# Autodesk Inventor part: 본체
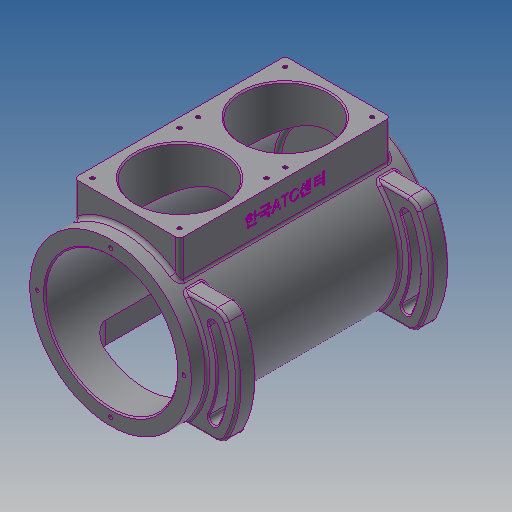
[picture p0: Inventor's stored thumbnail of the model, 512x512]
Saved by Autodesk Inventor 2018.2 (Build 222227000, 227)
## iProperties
Created: 2016-11
Part Number: 본체
Material: 알루미늄 6061
Document SubType Name: Modeling
Designer: mduedu
Density: 2.71 g/cm^3
Appearance: 기본값
Author: mduedu
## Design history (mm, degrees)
sketch "스케치1"
  geometry: C1 r 65 at (0, 0); 1 further point
  constraints: 1 centre point, 1 coincident
  dimensions: "d119" = 130 diameter of C1
extrude "돌출1" new body sketch "스케치1" distance "d3" = 98; taper "d4" = 0 deg; dims "d132" = 97, "d133" = 0
feature "쉘1" dims "d120" = 12, "d134" = 8
node "작업 평면2"
sketch "스케치13"
  geometry: L1 (42.5, 85)-(-42.5, 85); L2 (-42.5, 85)-(-42.5, -85); L3 (-42.5, -85)-(42.5, -85); L4 (42.5, -85)-(42.5, 85); 2 further points
  constraints: 8 end point, 2 parallel, 1 horizontal, 1 midpoint, 1 perpendicular, 1 vertical alignment
  dimensions: "d122" = 170 distance of L1.end L2.end; "d124" = 85 distance of L2.end L3.end; "d125" = 85 distance from line of point (0, 0) L1 (= 0.5 x d122)
extrude "돌출11" join sketch "스케치13" stored distance "d126" = 10; taper "d127" = 0 deg
sketch "스케치14"
  geometry: L1 (65, 97)-(-65, 97) reference; C1 r 35 at (0, 42.5); 1 further point
  constraints: 1 centre point, 1 vertical alignment
  dimensions: "d128" = 70 diameter of C1; "d129" = 54.5 distance from line of C1.centre L1
extrude "돌출12" cut sketch "스케치14" stored distance "d130" = 10; taper "d131" = 0 deg
sketch "스케치15"
  geometry: C1 r 53 at (0, 0) reference; 1 further point
extrude "돌출13" cut sketch "스케치15" stored distance "d135" = 10; taper "d136" = 0 deg
chamfer "모따기1" distance "d54" = 1; stored, may be unused: second distance "d55" = 2, angle "d56" = 45 deg
sketch "스케치8"
  geometry: C1 r 30 at (0, 0); C2 r 65 at (0, 0) reference; 1 further point
  constraints: 1 centre point, 1 concentric
  dimensions: "d57" = 60 diameter of C1
extrude "돌출8" join sketch "스케치8" distance "d58" = 14; taper "d59" = 0 deg
hole "구멍3" diameter "d62" = 41; stored, may be unused: countersink angle "d66" = 90 deg, drill point angle "d68" = 0 deg; dims "d63" = 6, "d64" = 47, "d65" = 14, "d67" = 17, "d195" = 10, "d196" = 10
fillet "모깎기11" dims "d69" = 3
fillet "모깎기12" dims "d70" = 3
fillet "모깎기13" dims "d71" = 0.3
chamfer "모따기2" distance "d72" = 1; stored, may be unused: second distance "d73" = 2, angle "d74" = 45 deg
node "작업 평면3"
sketch "스케치16"
  geometry: L1 (-42.5, -80)-(47.5, -80); L2 (-42.5, -80)-(21.14, -16.36); L3 (-42.5, -80)-(21.14, -143.64); L4 (3.462, -34.038)-(34.879, -34.038); L5 (3.462, -125.962)-(34.879, -125.962); A1 r 65 centre (-42.5, -80) between (3.462, -34.038) and (3.462, -125.962) reference; A2 r 90 centre (-42.5, -80) between (34.879, -125.962) and (34.879, -34.038); A3 r 90 centre (-42.5, -80) between (34.879, -34.038) and (34.879, -125.962); A4 r 65 centre (-42.5, -80) between (3.462, -125.962) and (3.462, -34.038); 1 further point
  constraints: 11 point on circle, 10 end point, 3 centre point, 2 parallel, 2 point on line, 1 coincident, 1 horizontal
  dimensions: "d140" = 45 deg angle of L3 L1; "d141" = 45 deg angle of L2 L1; "d142" = 25 radial gap between concentric circles of A1 A2
extrude "돌출14" join sketch "스케치16" distance "d143" = 15; taper "d144" = 0 deg
sketch "스케치17"
  geometry: L1 (-42.5, -80)-(34.414, -80); L2 (-42.5, -80)-(27.208, -47.495); L3 (-42.5, -80)-(27.208, -112.505); L4 (34.879, -34.038)-(3.462, -34.038) reference; L5 (3.462, -125.962)-(34.879, -125.962) reference; A1 r 65 centre (-42.5, -80) between (3.462, -34.038) and (3.462, -125.962) reference; A2 r 76.914 centre (-42.5, -80) between (19.17, -125.962) and (19.17, -34.038); A3 r 4 centre (27.208, -47.495) between (23.582, -49.185) and (30.833, -45.804); A4 r 4 centre (27.208, -112.505) between (30.833, -114.196) and (23.582, -110.815); A5 r 80.914 centre (-42.5, -80) between (30.833, -114.196) and (30.833, -45.804); A6 r 72.914 centre (-42.5, -80) between (23.582, -110.815) and (23.582, -49.185); 1 further point
  constraints: 13 point on circle, 6 end point, 5 centre point, 5 coincident, 3 midpoint, 2 point on line, 1 equal radius, 1 horizontal
  dimensions: "d145" = 25 deg angle of L1 L3; "d146" = 25 deg angle of L2 L1; "d147" = 8 diameter of A3
extrude "돌출15" cut sketch "스케치17" stored distance "d150" = 15; taper "d151" = 0 deg
fillet "모깎기17" dims "d152" = 10
fillet "모깎기18" dims "d153" = 2
fillet "모깎기19" dims "d154" = 2
chamfer "모따기4" distance "d155" = 1; stored, may be unused: second distance "d156" = 2, angle "d157" = 45 deg
fillet "모깎기20" dims "d159" = 3
fillet "모깎기21" dims "d160" = 3
fillet "모깎기22" dims "d161" = 3
node "작업 평면4"
sketch "스케치18"
  geometry: L1 (-42.5, 70)-(42.5, 70); L2 (42.5, 70)-(42.5, -70); L3 (42.5, -70)-(-42.5, -70); L4 (-42.5, -70)-(-42.5, 70); 2 further points
  constraints: 8 end point, 2 parallel, 1 horizontal, 1 midpoint, 1 perpendicular, 1 vertical alignment
  dimensions: "d162" = 140 distance of L1.end L2.end; "d164" = 85 distance of L2.end L3.end; "d165" = 70 distance from line of point (0, 0) L1 (= 0.5 x d162)
extrude "돌출16" cut sketch "스케치18" stored distance "d166" = 15; taper "d167" = 0 deg
fillet "모깎기23" dims "d168" = 10
fillet "모깎기24" dims "d173" = 3
sketch "스케치19"
  geometry: 4 further points
  constraints: 4 other
hole "구멍6" sketch "스케치19" at (0, -59), (59, 0), (-59, 0), (0, 59) diameter "d174" = 3.242; stored, may be unused: countersink angle "d178" = 90 deg, drill point angle "d180" = 120 deg; dims "d175" = 8, "d176" = 4, "d177" = 2, "d179" = 10
sketch "스케치20"
  geometry: L1 (35, -77.5)-(-35, -77.5); L2 (-35, -77.5)-(-35, -7.5); L3 (-35, -7.5)-(35, -7.5); L4 (35, -7.5)-(35, -77.5); L5 (35, -77.5)-(-35, -7.5); L6 (-35, -77.5)-(35, -7.5); C1 r 36 at (0, -42.5) reference; 5 further points
  constraints: 12 end point, 4 coincident, 2 midpoint, 2 parallel, 1 horizontal, 1 perpendicular
  dimensions: "d181" = 70 distance of L2.end L3.end; "d182" = 70 distance of L1.end L2.end
hole "구멍7" sketch "스케치20" at (-35, -77.5), (-35, -7.5), (35, -7.5), (35, -77.5) diameter "d183" = 3.242; stored, may be unused: countersink angle "d187" = 90 deg, drill point angle "d189" = 118 deg; dims "d184" = 8, "d185" = 4, "d186" = 2, "d188" = 10
sketch "스케치21"
  geometry: L1 (164, 0)-(0, 0) reference; L2 (-3, 0)-(-3, -24.649) reference; 3 further points
  constraints: 1 midpoint, 1 vertical alignment, 1 other
  dimensions: "d190" = 15 distance from line of point (82, -15) L1; "d191" = 85 distance from line of point (82, 0) L2 (derived)
feature "엠보싱2" sketch "스케치21" dims "d3" = 98, "d4" = 0, "d119" = 130, "d132" = 97, "d133" = 0, "d192" = 0.5, "d193" = 0
node "솔리드1"
mirror "대칭5"
mirror "대칭6"
mirror "대칭7"
